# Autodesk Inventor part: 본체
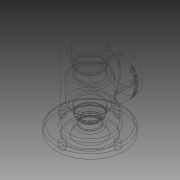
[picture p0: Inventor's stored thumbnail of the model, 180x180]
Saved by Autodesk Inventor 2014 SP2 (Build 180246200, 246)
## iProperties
Created: 2016-08
Part Number: 본체
Material: 일반
Document SubType Name: Modeling
Designer: 201-01
Density: 1 g/cm^3
Appearance: 기본값
Author: 201-01
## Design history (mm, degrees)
sketch "스케치1"
  geometry: C1 r 31 at (0, 0); 1 further point
  constraints: 1 centre point, 1 coincident
  dimensions: "d0" = 62 diameter of C1
extrude "돌출1" new body sketch "스케치1" distance "d1" = 102; taper "d2" = 0 deg
sketch "스케치2"
  geometry: C1 r 50 at (0, 0); 1 further point
  constraints: 1 centre point, 1 coincident
  dimensions: "d3" = 100 diameter of C1
extrude "돌출2" join sketch "스케치2" distance "d4" = 10; taper "d5" = 0 deg
sketch "스케치3"
  geometry: C1 r 31 at (0, 0); 1 further point
  constraints: 1 centre point, 1 coincident
  dimensions: "d6" = 62 diameter of C1
extrude "돌출3" join sketch "스케치3" distance "d7" = 3; taper "d8" = 0 deg
node "작업 평면1"
sketch "스케치4"
  geometry: L1 (31, 0)-(31, 102) reference; L2 (31, 102)-(-31, 102) reference; L3 (-31, 0)-(-31, 102) reference; L4 (50, 0)-(-50, 0) reference; C1 r 30 at (0, 46); 1 further point
  constraints: 1 centre point
  dimensions: "d10" = 60 diameter of C1; "d11" = 56 distance from line of L2 C1.centre; "d12" = 31 distance from line of L1 C1.centre
extrude "돌출4" join sketch "스케치4" stored distance "d13" = 3; taper "d14" = 0 deg
sketch "스케치5"
  geometry: 2 further points
  constraints: 1 coincident
hole "구멍1" sketch "스케치5" at (0, 0) diameter "d15" = 40.376; stored, may be unused: countersink angle "d19" = 90 deg, drill point angle "d21" = 0 deg; dims "d16" = 9, "d17" = 4, "d18" = 2, "d20" = 9
sketch "스케치6"
  geometry: C1 r 24 at (0, 0); 1 further point
  constraints: 1 centre point, 1 coincident
  dimensions: "d22" = 48 diameter of C1
extrude "돌출5" cut sketch "스케치6" distance "d23" = 3; taper "d24" = 0 deg
sketch "스케치11"
  geometry: C1 r 20 at (0, 0); 1 further point
  constraints: 1 centre point, 1 coincident
  dimensions: "d37" = 40 diameter of C1
extrude "돌출10" cut sketch "스케치11" distance "d38" = 9; taper "d39" = 0 deg
sketch "스케치12"
  geometry: C1 r 17.5 at (0, 0); 1 further point
  constraints: 1 centre point, 1 coincident
  dimensions: "d40" = 35 diameter of C1
extrude "돌출11" cut sketch "스케치12" distance "d41" = 3.25; taper "d42" = 0 deg
sketch "스케치13"
  geometry: C1 r 18.5 at (0, 0); 1 further point
  constraints: 1 centre point, 1 coincident
  dimensions: "d43" = 37 diameter of C1
extrude "돌출12" cut sketch "스케치13" distance "d44" = 1.75; taper "d45" = 0 deg
sketch "스케치14"
  geometry: C1 r 17.5 at (0, 0); 1 further point
  constraints: 1 centre point, 1 coincident
  dimensions: "d46" = 35 diameter of C1
extrude "돌출13" cut sketch "스케치14" distance "d47" = 11; taper "d48" = 0 deg
sketch "스케치15"
  geometry: C1 r 26 at (0, 0); 1 further point
  constraints: 1 centre point, 1 coincident
  dimensions: "d49" = 52 diameter of C1
extrude "돌출14" cut sketch "스케치15" distance "d50" = 38; taper "d51" = 0 deg
sketch "스케치16"
  geometry: C1 r 17.5 at (0, 0); 1 further point
  constraints: 1 centre point, 1 coincident
  dimensions: "d52" = 35 diameter of C1
extrude "돌출15" cut sketch "스케치16" distance "d53" = 11; taper "d54" = 0 deg
sketch "스케치17"
  geometry: C1 r 16.5 at (0, 0); 1 further point
  constraints: 1 centre point, 1 coincident
  dimensions: "d55" = 33 diameter of C1
extrude "돌출16" cut sketch "스케치17" distance "d56" = 5; taper "d57" = 0 deg
sketch "스케치18"
  geometry: C1 r 10 at (0, 0); 1 further point
  constraints: 1 centre point, 1 coincident
  dimensions: "d58" = 20 diameter of C1
extrude "돌출17" cut sketch "스케치18" distance "d59" = 2.7; taper "d60" = 0 deg
sketch "스케치19"
  geometry: C1 r 12.5 at (0, 0); 1 further point
  constraints: 1 centre point, 1 coincident
  dimensions: "d61" = 25 diameter of C1
extrude "돌출18" cut sketch "스케치19" distance "d62" = 7.3; taper "d63" = 0 deg
sketch "스케치20"
  geometry: C1 r 30 at (0, 0) reference; C2 r 19 at (0, 0); 1 further point
  constraints: 1 centre point, 1 coincident
  dimensions: "d64" = 38 diameter of C2
extrude "돌출19" cut sketch "스케치20" stored distance "d65" = 7.3; taper "d66" = 0 deg
sketch "스케치21"
  geometry: C1 r 19 at (0, 0) reference; 2 further points
  dimensions: "d67" = 24 distance of C1.centre point (0, 24)
hole "구멍2" sketch "스케치21" at (0, 24) diameter "d68" = 3.242; stored, may be unused: countersink angle "d72" = 90 deg, drill point angle "d74" = 0 deg; dims "d69" = 8, "d70" = 4, "d71" = 2, "d73" = 10
sketch "스케치22"
  geometry: C1 r 4 at (0, 41.5); 1 further point
  constraints: 1 centre point
  dimensions: "d78" = 8 diameter of C1; "d79" = 41.5 distance of point (0, 0) C1.centre
extrude "돌출20" cut sketch "스케치22" stored distance "d80" = 7.3; taper "d81" = 0 deg
node "작업 평면2"
sketch "스케치23"
  geometry: L1 (35.449, 66.739)-(35.449, 25.261); L2 (35.449, 25.261)-(42.551, 25.261); L3 (42.551, 25.261)-(42.551, 66.739); L4 (42.551, 66.739)-(35.449, 66.739); L5 (31, 102)-(-31, 102) reference; L6 (49, 76)-(49, 16) reference; 4 further points
  constraints: 2 midpoint, 1 horizontal alignment, 1 vertical alignment, 2 other
  dimensions: "d86" = 56 distance from line of L5 point (39, 46); "d87" = 10 distance from line of point (39, 46) L6
feature "엠보싱1" sketch "스케치23" dims "d0" = 62, "d88" = 0.5, "d89" = 0
chamfer "모따기1" distance "d90" = 1; stored, may be unused: second distance "d91" = 2, angle "d92" = 45 deg
chamfer "모따기2" distance "d93" = 1; stored, may be unused: second distance "d94" = 2, angle "d95" = 45 deg
chamfer "모따기3" distance "d96" = 1; stored, may be unused: second distance "d97" = 2, angle "d98" = 45 deg
fillet "모깎기1" dims "d99" = 0.3
fillet "모깎기2" dims "d100" = 3
fillet "모깎기3" dims "d101" = 3
sketch "스케치24"
  geometry: C1 r 16 at (0, 0); 1 further point
  constraints: 1 centre point, 1 coincident
  dimensions: "d102" = 32 diameter of C1
extrude "돌출21" cut sketch "스케치24" stored distance "d103" = 7.3; taper "d104" = 20 deg
fillet "모깎기4" dims "d105" = 3
chamfer "모따기4" distance "d106" = 0.7; stored, may be unused: second distance "d107" = 2, angle "d108" = 60 deg
fillet "모깎기6" dims "d110" = 3
node "솔리드1"
pattern_circular "원형 패턴1" dims angle "d76" = 360 deg
pattern_circular "원형 패턴2" dims angle "d83" = 360 deg
other parameters: "d9" = 49, "d85" = 31
